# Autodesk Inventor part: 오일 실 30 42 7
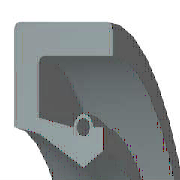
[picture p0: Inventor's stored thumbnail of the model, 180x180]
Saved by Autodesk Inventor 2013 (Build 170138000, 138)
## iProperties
IsCustomPart: 1
Created: 2012-02
Part Number: 오일 실 30 42 7
Material: 고무
Description: 오일 실 - 스프링 장착, 금속 케이스 SM
Document SubType Name: Modeling
Standard: JIS B 2402
Designer: mdu-01
Standards Organization: JIS
Language: ko-KR
Size Designation: 30 42 7 A
Categories: <MemberInstance><Categories><Category DisplayName="샤프트 부품" InternalName="7f7aeb1f-a693-4053-b835-cee3144e0d98" Mnemonic="SHFT"><Category DisplayName="실링" Intern
Density: 0.93 g/cm^3
Author: mdu-01
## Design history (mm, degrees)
body "Solid1"
revolve "회전1" stored, may be unused: angle "d33" = 360 deg
fillet "모깎기1" dims "d34" = 0.35 (= 0.05 x b)
chamfer "모따기1" distance "d35" = 0.7 (= 0.1 x b); stored, may be unused: second distance "d36" = 0.35 (= 0.05 x b), angle "d41" = 45 deg
sketch "스케치2"
  geometry: L1 (16.457, -5.158)-(17.021, -7); L2 (15.857, -4.55)-(16.457, -5.158); L3 (15, -1.75)-(15.857, -4.55); L4 (15.8, -0.875)-(15, -1.75); L5 (17.141, -0.875)-(15.8, -0.875); L6 (17.141, -1.575)-(17.141, -0.875); L7 (17.141, -5.25)-(17.141, -2.975); L8 (18.6, -5.25)-(17.141, -5.25); L9 (19.8, -1.75)-(18.6, -5.25); L10 (19.8, 0)-(19.8, -1.75); L11 (21, 0)-(19.8, 0); L12 (21, -7)-(21, 0); L13 (17.021, -7)-(21, -7); L14 (0, -9.6)-(0, 1.6) reference; L15 (28, 0)-(14, 0) reference; A1 r 0.7 centre (17.141, -2.275) between (17.141, -2.975) and (17.141, -1.575)
  constraints: 26 end point, 4 horizontal, 4 vertical, 2 point on circle, 1 centre point, 1 collinear, 1 parallel
  dimensions: "d2" = 7 distance of L12.start L11.start (= b); "d4" = 0.875 vertical distance of L10.start L5.start (= 0.125 x b); "d6" = 1.2 distance of L11.start L10.start (= 0.1 x dd - 0.1 x Diam); "d8" = 1.75 distance of L10.start L9.start (= 0.25 x b); "d10" = 1.75 vertical distance of L8.start L1.end (= 0.25 x b); "d12" = 1.2 horizontal distance of L9.start L8.start (= 0.1 x dd - 0.1 x Diam); "d14" = 0.7 radius of A1 (= 0.1 x b); "d16" = 0 horizontal distance of A1.centre L7.end; "d18" = 0.7 distance of L6.start L5.start (= 0.1 x b); "d20" = 0.8 horizontal distance of L4.start L3.start (= 0.0666667 x dd - 0.0666667 x Diam); "d22" = 0.12 horizontal distance of L7.start L1.end (= 0.01 x dd - 0.01 x Diam); "d24" = 0.875 vertical distance of L4.start L3.start (= 0.125 x b); "d26" = 2.8 vertical distance of L3.start L2.start (= 0.4 x b); "d28" = 0.85714 horizontal distance of L3.start L2.start (= 0.0714286 x dd - 0.0714286 x Diam); "d30" = 1.84211 vertical distance of L1.start L1.end (= 0.263158 x b); "d32" = 0.6 horizontal distance of L2.start L1.start (= 0.05 x dd - 0.05 x Diam); "d37" = 0 distance between parallel lines of L15 L11; "d38" = 21 distance between parallel lines of L14 L12 (= 0.5 x dd); "d39" = 15 distance from line of L14 L3.start (= 0.5 x Diam)
other parameters: "dd" = 42 [user parameter; used in 7 equation terms], "b" = 7 [user parameter; used in 12 equation terms], "d1" = 8 (derived), "d3" = 1 (derived), "d5" = 2 (derived), "d7" = 2 (derived), "d9" = 2 (derived), "d11" = 2 (derived), "d13" = 0.8 (derived), "d15" = 0 (derived), "d17" = 0.8 (derived), "d19" = 1.33333 (derived), "d21" = 0.2 (derived), "d23" = 1 (derived), "d25" = 3.2 (derived), "d27" = 1.42857 (derived), "d29" = 2.10526 (derived), "d31" = 1 (derived), "d40" = 0
